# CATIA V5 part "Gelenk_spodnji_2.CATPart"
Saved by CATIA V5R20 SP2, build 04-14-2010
Part number: Gelenk_spodnji_2
Bounding box of the stored display mesh (mm): x -4.8 to 4.8, y 0 to 25, z -29.795 to 29.795
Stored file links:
  C:\Documents and Settings\Administrator\My Documents\Hobi_dokumenti\CAD_CNC\Clap_CATIA\Gelenk_spodnji_2.CATPart
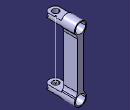
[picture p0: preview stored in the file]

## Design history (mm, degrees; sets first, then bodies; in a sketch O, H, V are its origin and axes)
Set1
  Point1: type Center, Curve edge [face of Pocket1 from Sketch2.L5 | face of Pocket2 from Sketch3.A1]
  Point2: type Center, Curve edge [face of Mirror1 | face of Mirror1]
  Line1: type PtPt, FirstPoint Point2, SecondPoint Point1
Body1 (main body)
  Sketch1 on xy-plane, origin (0, 0, 0), H (1, 0, 0), V (0, 1, 0)
    line L1 (0, 0) -> (-4.8, 0)
    line L2 (-4.8, 0) -> (-4.8, 25)
    line L3 (-4.8, 25) -> (0, 25)
    line L4 (0, 25) -> (0, 0)
    point P1 (-4.8, 0)
    point P3 (0, 25)
    distance O P1 = 4.8
    distance P3 O = 25
    horizontal: L1 H, L3 H
    vertical: L2 V, L4 V
    perpendicularity: L1 L2
  Shaft1: profile Sketch1, axis Sketch1.L4, angle 360
  Translate1: Direction xy-plane, Length 25, ToTransfor Shaft1
  Sketch2 on yz-plane, origin (0, 0, 0), H (0, 1, 0), V (0, 0, 1)
    line L1 (-3.9957, 30.9) -> (14, 30.9)
    line L2 (14, 30.9) -> (14, 26.9)
    line L3 (14, 26.9) -> (-3.9957, 26.9)
    line L4 (-3.9957, 26.9) -> (-3.9957, 30.9)
    point P5 (-3.9957, 23.1)
    line L5 (-3.9957, 23.1) -> (14, 23.1)
    line L6 (14, 23.1) -> (14, 19.1)
    line L7 (14, 19.1) -> (-3.9957, 19.1)
    line L8 (-3.9957, 19.1) -> (-3.9957, 23.1)
    point P7 (14, 19.1)
    reference projected line E1 through (0, 25) direction (1, 0) from axis of face of Shaft1 from Sketch1.L2
    reference projected line E2 through (0, 25) direction (1, 0) from axis of face of Shaft1 from Sketch1.L2
    reference projected line E3 (0, 29.8) -> (0, 20.2) from edge [face of Shaft1 from Sketch1.L1 | face of Shaft1 from Sketch1.L2]
    distance E1 L5 = 1.9
    distance E2 L3 = 1.9
    distance E3 L2 = 14
    length L8 = 4
    length L4 = 4
    horizontal: L1 H, L3 H, L5 H, L7 H
    vertical: L2 V, L4 V, L6 V, L8 V
    coincidence: P5 L4, P7 L2
  Pocket1: profile Sketch2, direction (1, 0, 0), length 20, mirrored extent
  Sketch3 on xy-plane, origin (0, 0, 0), H (1, 0, 0), V (0, 1, 0)
    circle A1 centre (0, 4.9462) radius 2.5
    point P1 (0, 4.9462)
    arc A2 centre (0, 4.9462) radius 5 from (-5, 4.9462) to (5, 4.9462) ccw
    line L1 (8.2326, 4.9462) -> (5, 4.9462)
    line L2 (-8.288, 4.9462) -> (-8.288, -1.7558)
    line L3 (-8.288, -1.7558) -> (8.2326, -1.7558)
    line L4 (8.2326, -1.7558) -> (8.2326, 4.9462)
    point P6 (-5, 4.9462)
    line L5 (-5, 4.9462) -> (-8.288, 4.9462)
    radius A1 = 2.5
    radius A2 = 5
    coincidence: P1 V, L1 P6
    horizontal: L1 H, L3 H, L5 H
    vertical: L2 V, L4 V
  Pocket2: profile Sketch3, direction (0, 0, 1), through (limit type 6)
  Mirror1: of the body so far, about xy-plane
  Sketch4 on face of Shaft1 from Sketch1.L3, origin (0, 25, 0), H (-1, 0, 0), V (0, 0, 1)
    line L1 (-2.5, 25) -> (2.5, 25)
    line L2 (2.5, 25) -> (2.5, -25)
    line L3 (2.5, -25) -> (-2.5, -25)
    line L4 (-2.5, -25) -> (-2.5, 25)
    distance V L2 = 2.5
    length L4 = 50
    distance H L3 = 25
    distance V L4 = 2.5
    horizontal: L1 H, L3 H
    vertical: L2 V, L4 V
  Pad1: profile Sketch4, direction (0, -1, 0), up to face of Pocket1 from Sketch2.L6
  Fillet1: radius 5, on edge [face of Shaft1 from Sketch1.L2 | face of Pad1 from Sketch4.L4]; edge [face of Pad1 from Sketch4.L2 | face of Shaft1 from Sketch1.L2]; edge [face of Pad1 from Sketch4.L4 | face of Mirror1]; edge [face of Mirror1 | face of Pad1 from Sketch4.L2]
  Sketch5 on face of Mirror1, origin (0, 25, 0), H (-1, 0, 0), V (0, 0, 1)
    circle A1 centre (0, 25) radius 4
    point P1 (0, 25)
    circle A2 centre (0, -25) radius 4
    point P2 (0, -25)
    reference intersected line E1 through (0, 0) direction (-1, 0) from xy-plane
    reference intersected line E2 through (0, 0) direction (0, -1) from yz-plane
    radius A1 = 4
    radius A2 = 4
    distance P2 H = 25
    distance P1 H = 25
    coincidence: P1 V, P2 V, E2 P1
    vertical: E2 V
    horizontal: E1 H
  Pocket3: profile Sketch5, direction (0, -1, 0), length 10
